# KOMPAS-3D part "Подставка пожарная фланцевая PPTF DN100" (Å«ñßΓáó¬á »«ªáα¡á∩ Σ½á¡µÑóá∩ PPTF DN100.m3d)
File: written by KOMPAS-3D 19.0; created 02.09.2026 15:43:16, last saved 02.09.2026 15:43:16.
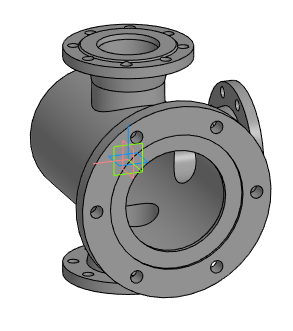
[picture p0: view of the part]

Document properties: Автор: Энергия; Полное имя файла: Z:\3.Личные\sachek\Dendor\_3D для проектировщиков\11.7 Тройник фланцевый с пожарной подставкой PPTF\PPTF_STP\Подставка пожарная фланцевая PPTF DN100.m3d

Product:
- Part/product: Подставка пожарная фланцевая PPTF DN100

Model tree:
1. Операция без истории:1  (labels: Подставка пожарная фланцевая PPTF DN100)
